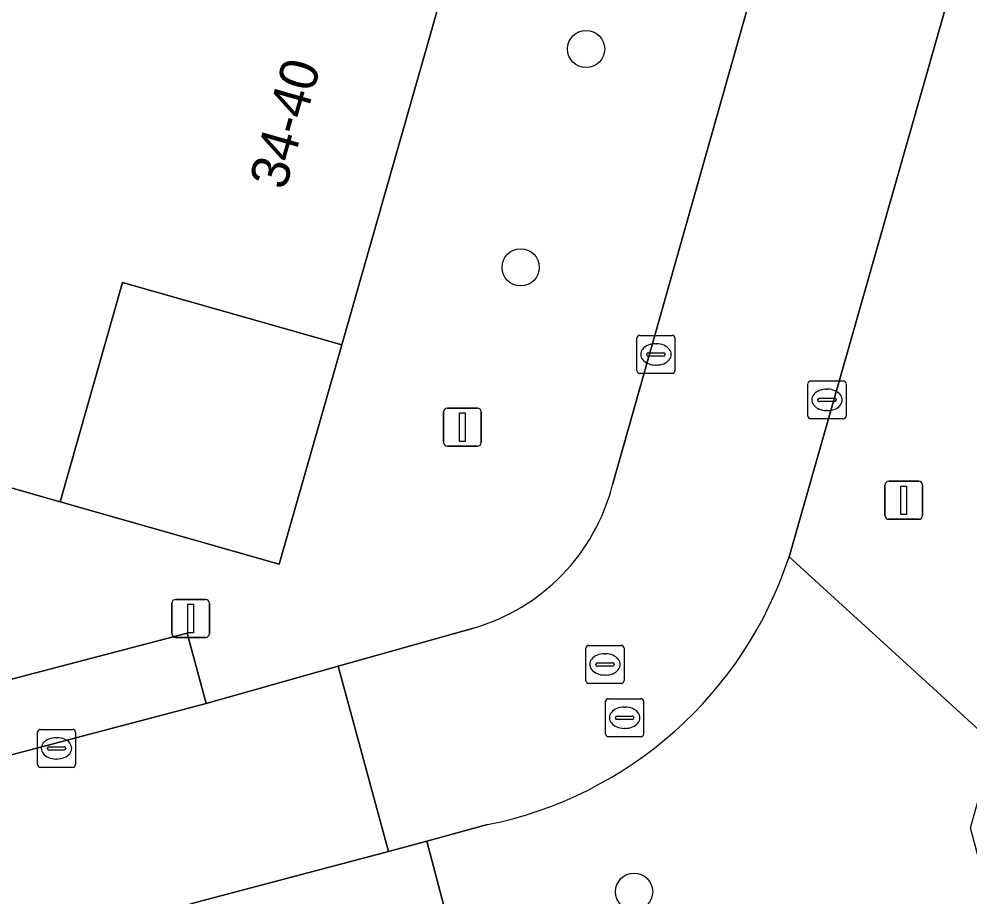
# Model space of a CAD drawing. Extents: x 162542 to 163147, y 380779 to 381521.
# Drawn here: x 163024.75 to 163049.77, y 381198.66 to 381221.75 of the extents above; entities that cross this region are included whole.
import ezdxf

# ---------------------------------------------------------------- set-up
doc = ezdxf.new("R2010")
doc.units = 0
for name, color, linetype in [('IMGEO_Boom', 7, 'Continuous'), ('IMGEO_Erf', 7, 'Continuous'), ('IMGEO_Groenvoorziening', 7, 'Continuous'), ('IMGEO_Kolk', 7, 'Continuous'), ('IMGEO_Lichtmast', 7, 'Continuous'), ('IMGEO_Muur', 7, 'Continuous'), ('IMGEO_Pand', 7, 'Continuous'), ('IMGEO_Pand_nummerreeks', 7, 'Continuous'), ('IMGEO_Parkeervlak_open', 7, 'Continuous'), ('IMGEO_Rijbaan_lokaal_open', 7, 'Continuous'), ('IMGEO_Rioolput', 7, 'Continuous'), ('IMGEO_Voetpad_open', 7, 'Continuous')]:
    doc.layers.add(name, color=color, linetype=linetype)

msp = doc.modelspace()

# ---------------------------------------------------------------- linework, layer by layer
at = {"layer": 'IMGEO_Boom'}
for centre in [(163039.671, 381220.961), (163037.949, 381215.217), (163040.934, 381198.794)]:
    msp.add_circle(centre, 0.489, dxfattribs=at)
at = {"layer": 'IMGEO_Erf'}
msp.add_lwpolyline([(163031.597, 381207.407), (163033.243, 381213.182), (163027.471, 381214.823), (163025.834, 381209.053)], close=True, dxfattribs=at)
at = {"layer": 'IMGEO_Groenvoorziening'}
msp.add_lwpolyline([(163035.481, 381200.125), (163034.468, 381199.853), (163029.293, 381198.489), (163030.813, 381192.679), (163037.007, 381194.327)], close=True, dxfattribs=at)
at = {"layer": 'IMGEO_Kolk'}
for p, q in [((163041.084, 381213.427), (163041.936, 381213.427)), ((163041.009, 381212.501), (163041.009, 381213.353)), ((163041.497, 381213.207), (163041.522, 381213.207)), ((163042.01, 381213.353), (163042.01, 381212.501)), ((163041.268, 381212.921), (163041.268, 381212.933)), ((163041.706, 381212.884), (163041.308, 381212.884)), ((163041.311, 381212.97), (163041.709, 381212.97)), ((163041.752, 381212.933), (163041.752, 381212.921)), ((163041.52, 381212.647), (163041.495, 381212.647)), ((163041.936, 381212.427), (163041.084, 381212.427)), ((163045.51, 381211.306), (163045.51, 381212.158)), ((163045.585, 381212.232), (163046.437, 381212.232)), ((163046.511, 381212.158), (163046.511, 381211.306)), ((163045.998, 381212.012), (163046.023, 381212.012)), ((163045.769, 381211.726), (163045.769, 381211.738)), ((163046.207, 381211.689), (163045.809, 381211.689)), ((163045.812, 381211.775), (163046.21, 381211.775)), ((163046.253, 381211.738), (163046.253, 381211.726)), ((163046.021, 381211.452), (163045.996, 381211.452)), ((163046.437, 381211.232), (163045.585, 381211.232)), ((163025.234, 381202.139), (163025.234, 381202.991)), ((163025.309, 381203.065), (163026.161, 381203.065)), ((163026.235, 381202.991), (163026.235, 381202.139)), ((163025.722, 381202.845), (163025.747, 381202.845)), ((163025.493, 381202.559), (163025.493, 381202.571)), ((163025.931, 381202.522), (163025.533, 381202.522)), ((163025.536, 381202.608), (163025.934, 381202.608)), ((163025.977, 381202.571), (163025.977, 381202.559)), ((163025.745, 381202.285), (163025.72, 381202.285)), ((163026.161, 381202.065), (163025.309, 381202.065))]:
    msp.add_line(p, q, dxfattribs=at)
for points in [[(163041.084, 381213.427), (163041.936, 381213.427)], [(163041.009, 381212.501), (163041.009, 381213.353)], [(163042.01, 381213.353), (163042.01, 381212.501)], [(163041.936, 381212.427), (163041.084, 381212.427)], [(163045.51, 381211.306), (163045.51, 381212.158)], [(163045.585, 381212.232), (163046.437, 381212.232)], [(163046.511, 381212.158), (163046.511, 381211.306)], [(163046.437, 381211.232), (163045.585, 381211.232)], [(163025.234, 381202.139), (163025.234, 381202.991)], [(163025.309, 381203.065), (163026.161, 381203.065)], [(163026.235, 381202.991), (163026.235, 381202.139)], [(163026.161, 381202.065), (163025.309, 381202.065)]]:
    msp.add_lwpolyline(points, dxfattribs=at)
for centre, radius, start, end in [((163041.086, 381213.351), 0.0765, 91.552, 178.448), ((163041.086, 381213.351), 0.0765, 91.552, 178.448), ((163041.934, 381213.351), 0.0765, 1.552, 88.448), ((163041.934, 381213.351), 0.0765, 1.552, 88.448), ((163041.308, 381212.93), 0.0403, 85.8775, 175.7526), ((163041.305, 381212.92), 0.0366, 178.938, 274.7102), ((163041.709, 381212.927), 0.043, 264.8664, 352.4533), ((163041.713, 381212.932), 0.0386, 1.7309, 96.639), ((163041.086, 381212.503), 0.0765, 181.552, 268.448), ((163041.086, 381212.503), 0.0765, 181.552, 268.448), ((163041.934, 381212.503), 0.0765, 271.552, 358.448), ((163041.934, 381212.503), 0.0765, 271.552, 358.448), ((163045.587, 381212.156), 0.0765, 91.552, 178.448), ((163045.587, 381212.156), 0.0765, 91.552, 178.448), ((163046.435, 381212.156), 0.0765, 1.552, 88.448), ((163046.435, 381212.156), 0.0765, 1.552, 88.448), ((163045.809, 381211.735), 0.0403, 85.8775, 175.7526), ((163045.806, 381211.725), 0.0366, 178.938, 274.7102), ((163046.21, 381211.732), 0.043, 264.8664, 352.4533), ((163046.214, 381211.737), 0.0386, 1.7309, 96.639), ((163045.587, 381211.308), 0.0765, 181.552, 268.448), ((163045.587, 381211.308), 0.0765, 181.552, 268.448), ((163046.435, 381211.308), 0.0765, 271.552, 358.448), ((163046.435, 381211.308), 0.0765, 271.552, 358.448), ((163025.311, 381202.989), 0.0765, 91.552, 178.448), ((163025.311, 381202.989), 0.0765, 91.552, 178.448), ((163026.159, 381202.989), 0.0765, 1.552, 88.448), ((163026.159, 381202.989), 0.0765, 1.552, 88.448), ((163025.533, 381202.568), 0.0403, 85.8775, 175.7526), ((163025.53, 381202.558), 0.0366, 178.938, 274.7102), ((163025.934, 381202.565), 0.043, 264.8664, 352.4533), ((163025.938, 381202.57), 0.0386, 1.7309, 96.639), ((163025.311, 381202.141), 0.0765, 181.552, 268.448), ((163025.311, 381202.141), 0.0765, 181.552, 268.448), ((163026.159, 381202.141), 0.0765, 271.552, 358.448), ((163026.159, 381202.141), 0.0765, 271.552, 358.448)]:
    msp.add_arc(centre, radius, start, end, dxfattribs=at)
for centre, major_axis, ratio, start_param, end_param in [((163041.496, 381212.927), (-0.387, 0.002), 0.722429, 4.712389, 7.853982), ((163041.521, 381212.927), (-0.39, 0.002), 0.717154, 1.570796, 4.712389), ((163045.997, 381211.732), (-0.387, 0.002), 0.722429, 4.712389, 7.853982), ((163046.022, 381211.732), (-0.39, 0.002), 0.717154, 1.570796, 4.712389), ((163025.721, 381202.565), (-0.387, 0.002), 0.722429, 4.712389, 7.853982), ((163025.746, 381202.565), (-0.39, 0.002), 0.717154, 1.570796, 4.712389)]:
    msp.add_ellipse(centre, major_axis=major_axis, ratio=ratio, start_param=start_param, end_param=end_param, dxfattribs=at)
at = {"layer": 'IMGEO_Lichtmast'}
for p, q in [((163035.921, 381210.614), (163035.921, 381211.414)), ((163035.921, 381211.414), (163035.921, 381210.614)), ((163036.021, 381211.514), (163036.811, 381211.514)), ((163036.811, 381211.514), (163036.021, 381211.514)), ((163036.911, 381211.414), (163036.911, 381210.614)), ((163036.911, 381210.614), (163036.911, 381211.414)), ((163036.811, 381210.514), (163036.021, 381210.514)), ((163036.021, 381210.514), (163036.811, 381210.514)), ((163047.535, 381208.69), (163047.535, 381209.49)), ((163047.535, 381209.49), (163047.535, 381208.69)), ((163047.635, 381209.59), (163048.425, 381209.59)), ((163048.425, 381209.59), (163047.635, 381209.59)), ((163048.525, 381209.49), (163048.525, 381208.69)), ((163048.525, 381208.69), (163048.525, 381209.49)), ((163048.425, 381208.59), (163047.635, 381208.59)), ((163047.635, 381208.59), (163048.425, 381208.59)), ((163028.768, 381205.583), (163028.768, 381206.383)), ((163028.768, 381206.383), (163028.768, 381205.583)), ((163028.868, 381206.483), (163029.658, 381206.483)), ((163029.658, 381206.483), (163028.868, 381206.483)), ((163029.758, 381206.383), (163029.758, 381205.583)), ((163029.758, 381205.583), (163029.758, 381206.383)), ((163029.658, 381205.483), (163028.868, 381205.483)), ((163028.868, 381205.483), (163029.658, 381205.483))]:
    msp.add_line(p, q, dxfattribs=at)
for points in [[(163036.341, 381211.389), (163036.491, 381211.389), (163036.491, 381210.639), (163036.341, 381210.639), (163036.341, 381211.389)], [(163047.955, 381209.465), (163048.105, 381209.465), (163048.105, 381208.715), (163047.955, 381208.715), (163047.955, 381209.465)], [(163029.188, 381206.358), (163029.338, 381206.358), (163029.338, 381205.608), (163029.188, 381205.608), (163029.188, 381206.358)]]:
    msp.add_lwpolyline(points, dxfattribs=at)
for centre, start, end in [((163036.021, 381211.414), 90, 180), ((163036.021, 381211.414), 90, 180), ((163036.811, 381211.414), 0, 90), ((163036.811, 381211.414), 360, 90), ((163036.021, 381210.614), 180, 270), ((163036.021, 381210.614), 180, 270), ((163036.811, 381210.614), 270, 0), ((163036.811, 381210.614), 270, 0), ((163047.635, 381209.49), 90, 180), ((163047.635, 381209.49), 90, 180), ((163048.425, 381209.49), 0, 90), ((163048.425, 381209.49), 360, 90), ((163047.635, 381208.69), 180, 270), ((163047.635, 381208.69), 180, 270), ((163048.425, 381208.69), 270, 0), ((163048.425, 381208.69), 270, 0), ((163028.868, 381206.383), 90, 180), ((163028.868, 381206.383), 90, 180), ((163029.658, 381206.383), 0, 90), ((163029.658, 381206.383), 360, 90), ((163028.868, 381205.583), 180, 270), ((163028.868, 381205.583), 180, 270), ((163029.658, 381205.583), 270, 0), ((163029.658, 381205.583), 270, 0)]:
    msp.add_arc(centre, 0.1, start, end, dxfattribs=at)
at = {"layer": 'IMGEO_Muur'}
for points in [[(163033.243, 381213.182), (163031.597, 381207.407)], [(163031.597, 381207.407), (163025.834, 381209.053)]]:
    msp.add_lwpolyline(points, dxfattribs=at)
at = {"layer": 'IMGEO_Pand'}
msp.add_lwpolyline([(163032.532, 381232.569), (163031.337, 381232.908), (163030.25, 381233.217), (163020.904, 381235.873), (163014.779, 381237.614), (163008.089, 381214.101), (163012.206, 381212.93), (163025.834, 381209.053), (163027.471, 381214.823), (163033.243, 381213.182), (163036.655, 381225.146), (163030.88, 381226.797)], close=True, dxfattribs=at)
at = {"layer": 'IMGEO_Parkeervlak_open'}
msp.add_lwpolyline([(162945.307, 381183.409), (162944.204, 381183.118), (162943.854, 381183.025), (162937.074, 381181.191), (162920.542, 381176.676), (162920.963, 381174.947), (162923.178, 381175.528), (162939.834, 381180.075), (163029.671, 381203.749), (163029.17, 381205.595), (163009.881, 381200.547), (163008.469, 381200.178), (162968.263, 381189.504)], close=True, dxfattribs=at)
at = {"layer": 'IMGEO_Rijbaan_lokaal_open'}
for points in [[(163046.17, 381230.006), (163040.367, 381209.493)], [(163045.012, 381207.602), (163050.51, 381226.879)], [(163036.711, 381205.731), (163033.144, 381204.725), (163034.468, 381199.853), (163035.481, 381200.125), (163037.079, 381200.56)], [(162994.468, 381189.311), (163004.787, 381192.03), (163005.956, 381192.338), (163016.547, 381195.13), (163017.711, 381195.436), (163023.16, 381196.872), (163028.123, 381198.18), (163029.293, 381198.489), (163034.468, 381199.853), (163033.144, 381204.725), (163029.671, 381203.749), (162939.834, 381180.075)]]:
    msp.add_lwpolyline(points, dxfattribs=at)
for centre, radius, start, end in [((163035.247, 381210.811), 5.287, 286.0728, 345.5646), ((163035.007, 381210.884), 10.529, 281.349, 341.8409)]:
    msp.add_arc(centre, radius, start, end, dxfattribs=at)
at = {"layer": 'IMGEO_Rioolput'}
for p, q in [((163039.668, 381204.347), (163039.668, 381205.199)), ((163039.743, 381205.273), (163040.595, 381205.273)), ((163040.669, 381205.199), (163040.669, 381204.347)), ((163040.156, 381205.053), (163040.181, 381205.053)), ((163039.927, 381204.767), (163039.927, 381204.779)), ((163040.365, 381204.73), (163039.967, 381204.73)), ((163039.97, 381204.816), (163040.368, 381204.816)), ((163040.411, 381204.779), (163040.411, 381204.767)), ((163040.179, 381204.493), (163040.154, 381204.493)), ((163040.595, 381204.273), (163039.743, 381204.273)), ((163040.26, 381203.871), (163041.112, 381203.871)), ((163040.185, 381202.945), (163040.185, 381203.797)), ((163040.673, 381203.651), (163040.698, 381203.651)), ((163041.186, 381203.797), (163041.186, 381202.945)), ((163040.444, 381203.365), (163040.444, 381203.377)), ((163040.487, 381203.414), (163040.885, 381203.414)), ((163040.928, 381203.377), (163040.928, 381203.365)), ((163040.882, 381203.328), (163040.484, 381203.328)), ((163041.112, 381202.871), (163040.26, 381202.871)), ((163040.696, 381203.091), (163040.671, 381203.091))]:
    msp.add_line(p, q, dxfattribs=at)
for points in [[(163039.668, 381204.347), (163039.668, 381205.199)], [(163039.743, 381205.273), (163040.595, 381205.273)], [(163040.669, 381205.199), (163040.669, 381204.347)], [(163040.595, 381204.273), (163039.743, 381204.273)], [(163040.26, 381203.871), (163041.112, 381203.871)], [(163040.185, 381202.945), (163040.185, 381203.797)], [(163041.186, 381203.797), (163041.186, 381202.945)], [(163041.112, 381202.871), (163040.26, 381202.871)]]:
    msp.add_lwpolyline(points, dxfattribs=at)
for centre, radius, start, end in [((163039.745, 381205.197), 0.0765, 91.552, 178.448), ((163039.745, 381205.197), 0.0765, 91.552, 178.448), ((163040.593, 381205.197), 0.0765, 1.552, 88.448), ((163040.593, 381205.197), 0.0765, 1.552, 88.448), ((163039.967, 381204.776), 0.0403, 85.8775, 175.7526), ((163039.964, 381204.766), 0.0366, 178.938, 274.7102), ((163040.368, 381204.773), 0.043, 264.8664, 352.4533), ((163040.372, 381204.778), 0.0386, 1.7309, 96.639), ((163039.745, 381204.349), 0.0765, 181.552, 268.448), ((163039.745, 381204.349), 0.0765, 181.552, 268.448), ((163040.593, 381204.349), 0.0765, 271.552, 358.448), ((163040.593, 381204.349), 0.0765, 271.552, 358.448), ((163040.262, 381203.795), 0.0765, 91.552, 178.448), ((163040.262, 381203.795), 0.0765, 91.552, 178.448), ((163041.11, 381203.795), 0.0765, 1.552, 88.448), ((163041.11, 381203.795), 0.0765, 1.552, 88.448), ((163040.484, 381203.374), 0.0403, 85.8775, 175.7526), ((163040.889, 381203.376), 0.0386, 1.7309, 96.639), ((163040.481, 381203.364), 0.0366, 178.938, 274.7102), ((163040.885, 381203.371), 0.043, 264.8664, 352.4533), ((163040.262, 381202.947), 0.0765, 181.552, 268.448), ((163040.262, 381202.947), 0.0765, 181.552, 268.448), ((163041.11, 381202.947), 0.0765, 271.552, 358.448), ((163041.11, 381202.947), 0.0765, 271.552, 358.448)]:
    msp.add_arc(centre, radius, start, end, dxfattribs=at)
for centre, major_axis, ratio, start_param, end_param in [((163040.155, 381204.773), (-0.387, 0.002), 0.722429, 4.712389, 7.853982), ((163040.18, 381204.773), (-0.39, 0.002), 0.717154, 1.570796, 4.712389), ((163040.672, 381203.371), (-0.387, 0.002), 0.722429, 4.712389, 7.853982), ((163040.697, 381203.371), (-0.39, 0.002), 0.717154, 1.570796, 4.712389)]:
    msp.add_ellipse(centre, major_axis=major_axis, ratio=ratio, start_param=start_param, end_param=end_param, dxfattribs=at)
at = {"layer": 'IMGEO_Voetpad_open'}
for points in [[(163044.895, 381234.361), (163042.716, 381236.69), (163042.332, 381237.099), (163037.981, 381232.912), (163038.295, 381230.92), (163036.655, 381225.146), (163033.243, 381213.182), (163031.597, 381207.407), (163025.834, 381209.053), (163012.206, 381212.93), (163011.346, 381209.724), (163010.781, 381207.905), (163009.272, 381202.57), (163003.712, 381201.081), (162966.985, 381191.284), (162966.757, 381191.138), (162968.263, 381189.504), (163008.469, 381200.178), (163009.881, 381200.547), (163029.17, 381205.595), (163029.671, 381203.749), (163033.144, 381204.725), (163036.711, 381205.731)], [(163040.367, 381209.493), (163046.17, 381230.006)], [(163005.842, 381183.958), (163048.392, 381195.282), (163050.98, 381195.991), (163049.784, 381200.477), (163050.413, 381202.683), (163045.012, 381207.602)], [(163037.079, 381200.56), (163035.481, 381200.125), (163037.007, 381194.327), (163030.813, 381192.679), (163029.667, 381192.374), (163024.694, 381191.05), (163019.244, 381189.6), (163018.097, 381189.294), (163007.54, 381186.484), (163006.379, 381186.176), (162996.039, 381183.424)]]:
    msp.add_lwpolyline(points, dxfattribs=at)
msp.add_lwpolyline([(163054.725, 381219.532), (163057.157, 381228.09), (163057.755, 381230.408), (163055.304, 381229.374), (163054.426, 381225.777), (163050.51, 381226.879), (163045.012, 381207.602), (163050.413, 381202.683), (163051.416, 381208), (163051.506, 381208.345)], close=True, dxfattribs=at)
for centre, radius, start, end in [((163035.247, 381210.811), 5.287, 286.0728, 345.5646), ((163035.007, 381210.884), 10.529, 281.349, 341.8409)]:
    msp.add_arc(centre, radius, start, end, dxfattribs=at)

# ---------------------------------------------------------------- texts
at = {"layer": 'IMGEO_Pand_nummerreeks'}
msp.add_text('34-40', height=1, rotation=74.1036, dxfattribs=at).set_placement((163031.755, 381217.225))

doc.saveas('drawing.dxf')
